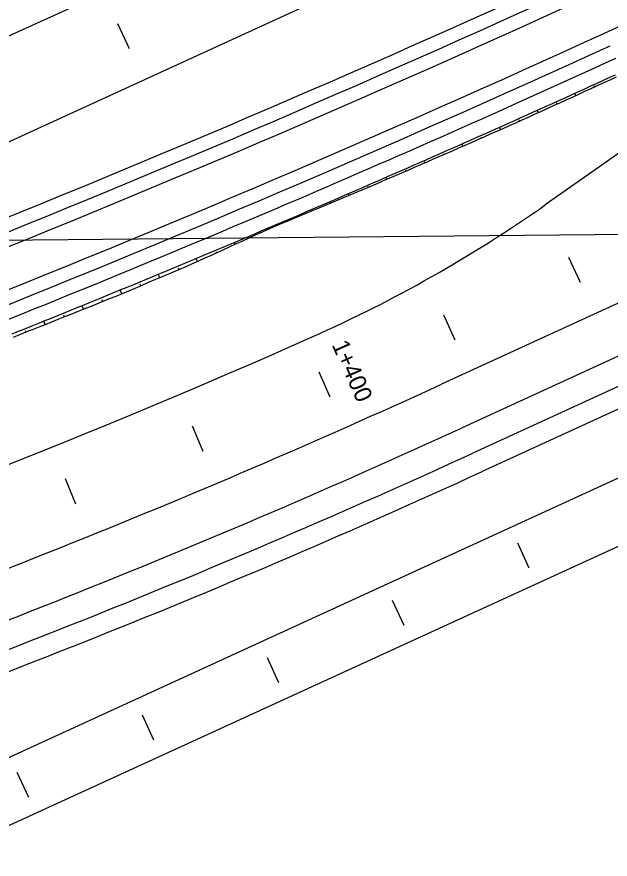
# Model space of a CAD drawing. Extents: x 6503541 to 6503743, y 5888004 to 5888145.
# Drawn here: x 6503623.308 to 6503624.343, y 5888063.051 to 5888064.519 of the extents above; entities that cross this region are included whole.
import ezdxf

# ---------------------------------------------------------------- set-up
doc = ezdxf.new("R2010")
doc.units = 0
doc.layers.add('12', color=7, linetype='Continuous')
doc.layers.add('tabela', color=7, linetype='Continuous')

msp = doc.modelspace()

# ---------------------------------------------------------------- linework, layer by layer
at = {"layer": '12'}
for p, q in [((6503624.3329, 5888064.491), (6503641.7733, 5888072.4873)), ((6503626.2595, 5888065.6608), (6503622.6026, 5888063.9841)), ((6503627.5672, 5888065.187), (6503623.1172, 5888063.1467)), ((6503626.551, 5888065.0262), (6503624.0486, 5888063.8788)), ((6503624.4101, 5888064.9977), (6503622.5325, 5888064.1368)), ((6503626.8132, 5888065.0011), (6503624.1036, 5888063.7588)), ((6503626.8282, 5888064.9684), (6503624.1186, 5888063.7261)), ((6503626.5424, 5888064.9298), (6503624.0836, 5888063.8025)), ((6503624.6932, 5888064.5176), (6503624.2296, 5888064.1916)), ((6503624.3147, 5888064.3992), (6503624.3155, 5888064.3974)), ((6503624.2828, 5888064.3824), (6503624.2811, 5888064.3861)), ((6503624.2492, 5888064.3693), (6503624.2501, 5888064.3674)), ((6503624.2173, 5888064.3525), (6503624.2155, 5888064.3565)), ((6503624.1836, 5888064.3397), (6503624.1845, 5888064.3377)), ((6503624.1517, 5888064.3229), (6503624.1498, 5888064.327)), ((6503624.1178, 5888064.3104), (6503624.1187, 5888064.3084)), ((6503624.0858, 5888064.2939), (6503624.0841, 5888064.2978)), ((6503624.052, 5888064.2813), (6503624.0528, 5888064.2795)), ((6503624.0198, 5888064.2651), (6503624.0182, 5888064.2687)), ((6503623.986, 5888064.2525), (6503623.9867, 5888064.2508)), ((6503623.9537, 5888064.2365), (6503623.9523, 5888064.2398)), ((6503623.92, 5888064.2238), (6503623.9207, 5888064.2221)), ((6503623.8875, 5888064.2082), (6503623.8863, 5888064.2111)), ((6503623.8537, 5888064.1956), (6503623.8543, 5888064.1944)), ((6503623.821, 5888064.1806), (6503623.8201, 5888064.1827)), ((6503623.7874, 5888064.1677), (6503623.7877, 5888064.1668)), ((6503623.7546, 5888064.1529), (6503623.7539, 5888064.1544)), ((6503623.689, 5888064.123), (6503623.6876, 5888064.1263)), ((6503623.7213, 5888064.1391), (6503623.7218, 5888064.1379)), ((6503623.6235, 5888064.0933), (6503623.6212, 5888064.0984)), ((6503623.6553, 5888064.1102), (6503623.6562, 5888064.1081)), ((6503625.4167, 5888064.0822), (6503623.1671, 5888063.0508)), ((6503623.5893, 5888064.0816), (6503623.5905, 5888064.0788)), ((6503623.5574, 5888064.0647), (6503623.5548, 5888064.0707)), ((6503623.5229, 5888064.0538), (6503623.5243, 5888064.0506)), ((6503623.4911, 5888064.0367), (6503623.4883, 5888064.0433)), ((6503623.4564, 5888064.0264), (6503623.4577, 5888064.0232)), ((6503623.4243, 5888064.0097), (6503623.4218, 5888064.016)), ((6503623.3897, 5888063.9994), (6503623.3909, 5888063.9964)), ((6503623.3574, 5888063.983), (6503623.3551, 5888063.9889)), ((6503623.3228, 5888063.9726), (6503623.324, 5888063.9697))]:
    msp.add_line(p, q, dxfattribs=at)
for points in [[(6503623.5045, 5888064.4637), (6503623.4845, 5888064.5073)], [(6503623.2999, 5888063.9667), (6503623.3111, 5888063.9712), (6503623.3223, 5888063.9757), (6503623.3335, 5888063.9802), (6503623.3447, 5888063.9847), (6503623.3558, 5888063.9892), (6503623.367, 5888063.9937), (6503623.3782, 5888063.9982), (6503623.3894, 5888064.0028), (6503623.4005, 5888064.0073), (6503623.4117, 5888064.0119), (6503623.4229, 5888064.0164), (6503623.434, 5888064.021), (6503623.4452, 5888064.0255), (6503623.4563, 5888064.0301), (6503623.4675, 5888064.0347), (6503623.4786, 5888064.0393), (6503623.4898, 5888064.0438), (6503623.5009, 5888064.0484), (6503623.5121, 5888064.053), (6503623.5232, 5888064.0576), (6503623.5343, 5888064.0622), (6503623.5455, 5888064.0668), (6503623.5566, 5888064.0715), (6503623.5678, 5888064.0761), (6503623.5789, 5888064.0807), (6503623.59, 5888064.0853), (6503623.6011, 5888064.09), (6503623.6123, 5888064.0946), (6503623.6234, 5888064.0993), (6503623.6345, 5888064.1039), (6503623.6456, 5888064.1086), (6503623.6567, 5888064.1133), (6503623.6678, 5888064.1179), (6503623.679, 5888064.1226), (6503623.6901, 5888064.1273), (6503623.7012, 5888064.132), (6503623.7123, 5888064.1367), (6503623.7234, 5888064.1414), (6503623.7345, 5888064.1461), (6503623.7456, 5888064.1508), (6503623.7567, 5888064.1555), (6503623.7677, 5888064.1603), (6503623.7788, 5888064.165), (6503623.7899, 5888064.1697), (6503623.801, 5888064.1745), (6503623.8121, 5888064.1792), (6503623.8232, 5888064.184), (6503623.8342, 5888064.1887), (6503623.8453, 5888064.1935), (6503623.8564, 5888064.1982), (6503623.8674, 5888064.203), (6503623.8785, 5888064.2078), (6503623.8896, 5888064.2126), (6503623.9006, 5888064.2174), (6503623.9117, 5888064.2222), (6503623.9228, 5888064.227), (6503623.9338, 5888064.2318), (6503623.9449, 5888064.2366), (6503623.9559, 5888064.2414), (6503623.967, 5888064.2462), (6503623.978, 5888064.251), (6503623.9891, 5888064.2559), (6503624.0001, 5888064.2607), (6503624.0111, 5888064.2656), (6503624.0222, 5888064.2704), (6503624.0332, 5888064.2753), (6503624.0442, 5888064.2801), (6503624.0553, 5888064.285), (6503624.0663, 5888064.2899), (6503624.0773, 5888064.2947), (6503624.0883, 5888064.2996), (6503624.0993, 5888064.3045), (6503624.1104, 5888064.3094), (6503624.1214, 5888064.3143), (6503624.1324, 5888064.3192), (6503624.1434, 5888064.3241), (6503624.1544, 5888064.329), (6503624.1654, 5888064.334), (6503624.1764, 5888064.3389), (6503624.1874, 5888064.3438), (6503624.1984, 5888064.3488), (6503624.2094, 5888064.3537), (6503624.2204, 5888064.3587), (6503624.2314, 5888064.3636), (6503624.2424, 5888064.3686), (6503624.2533, 5888064.3735), (6503624.2643, 5888064.3785), (6503624.2753, 5888064.3835), (6503624.2863, 5888064.3885), (6503624.2973, 5888064.3935), (6503624.3082, 5888064.3985), (6503624.3192, 5888064.4035), (6503624.3302, 5888064.4085), (6503624.3411, 5888064.4135), (6503624.3521, 5888064.4185)], [(6503623.3022, 5888063.9611), (6503623.3134, 5888063.9655), (6503623.3246, 5888063.97), (6503623.3358, 5888063.9744), (6503623.347, 5888063.9789), (6503623.3582, 5888063.9833), (6503623.3694, 5888063.9878), (6503623.3806, 5888063.9922), (6503623.3918, 5888063.9967), (6503623.403, 5888064.0012), (6503623.4142, 5888064.0057), (6503623.4254, 5888064.0102), (6503623.4366, 5888064.0147), (6503623.4478, 5888064.0192), (6503623.459, 5888064.0237), (6503623.4701, 5888064.0282), (6503623.4813, 5888064.0327), (6503623.4925, 5888064.0372), (6503623.5036, 5888064.0419), (6503623.5147, 5888064.0466), (6503623.5258, 5888064.0513), (6503623.5369, 5888064.056), (6503623.548, 5888064.0607), (6503623.5591, 5888064.0654), (6503623.5702, 5888064.0701), (6503623.5813, 5888064.0748), (6503623.5924, 5888064.0796), (6503623.6035, 5888064.0843), (6503623.6145, 5888064.0892), (6503623.6255, 5888064.0942), (6503623.6365, 5888064.0992), (6503623.6475, 5888064.1042), (6503623.6585, 5888064.1091), (6503623.6694, 5888064.1141), (6503623.6804, 5888064.1191), (6503623.6914, 5888064.1241), (6503623.7024, 5888064.1291), (6503623.7134, 5888064.1341), (6503623.7243, 5888064.1391), (6503623.7353, 5888064.1441), (6503623.7463, 5888064.1491), (6503623.7573, 5888064.1541), (6503623.7683, 5888064.1588), (6503623.7795, 5888064.1634), (6503623.7906, 5888064.168), (6503623.8018, 5888064.1726), (6503623.8129, 5888064.1772), (6503623.8241, 5888064.1818), (6503623.8352, 5888064.1864), (6503623.8463, 5888064.1911), (6503623.8575, 5888064.1957), (6503623.8686, 5888064.2003), (6503623.8797, 5888064.205), (6503623.8909, 5888064.2096), (6503623.902, 5888064.2143), (6503623.9131, 5888064.2189), (6503623.9242, 5888064.2236), (6503623.9353, 5888064.2284), (6503623.9463, 5888064.2333), (6503623.9574, 5888064.2381), (6503623.9684, 5888064.2429), (6503623.9795, 5888064.2477), (6503623.9906, 5888064.2524), (6503624.0016, 5888064.2572), (6503624.0127, 5888064.262), (6503624.0237, 5888064.2668), (6503624.0348, 5888064.2717), (6503624.0458, 5888064.2765), (6503624.0569, 5888064.2813), (6503624.0679, 5888064.2861), (6503624.079, 5888064.291), (6503624.09, 5888064.2958), (6503624.1011, 5888064.3006), (6503624.1121, 5888064.3055), (6503624.1231, 5888064.3103), (6503624.1342, 5888064.3152), (6503624.1452, 5888064.3201), (6503624.1562, 5888064.3249), (6503624.1672, 5888064.3299), (6503624.1782, 5888064.3348), (6503624.1892, 5888064.3398), (6503624.2002, 5888064.3448), (6503624.2112, 5888064.3498), (6503624.2222, 5888064.3547), (6503624.2331, 5888064.3597), (6503624.2441, 5888064.3647), (6503624.2551, 5888064.3697), (6503624.2661, 5888064.3747), (6503624.277, 5888064.3797), (6503624.288, 5888064.3847), (6503624.2989, 5888064.3897), (6503624.3099, 5888064.3948), (6503624.3209, 5888064.3998), (6503624.3318, 5888064.4048), (6503624.3428, 5888064.4099), (6503624.3538, 5888064.4148)], [(6503624.2911, 5888064.056), (6503624.2711, 5888064.0996)], [(6503624.0729, 5888063.956), (6503624.0529, 5888063.9996)], [(6503623.8346, 5888063.9008), (6503623.854, 5888063.8569)], [(6503623.6334, 5888063.7614), (6503623.6147, 5888063.8056)], [(6503623.4112, 5888063.6695), (6503623.3933, 5888063.714)], [(6503624.2017, 5888063.5582), (6503624.1817, 5888063.6018)], [(6503623.9835, 5888063.4582), (6503623.9635, 5888063.5018)], [(6503623.7654, 5888063.3581), (6503623.7454, 5888063.4018)], [(6503623.5472, 5888063.2581), (6503623.5272, 5888063.3017)], [(6503623.329, 5888063.1581), (6503623.309, 5888063.2017)]]:
    msp.add_lwpolyline(points, dxfattribs=at)
for centre, radius, start, end in [((6503614.3158, 5888086.3389), 23.9172, 291.63106, 294.63106), ((6503614.3158, 5888086.3389), 23.9412, 291.63106, 294.63106), ((6503614.3158, 5888086.3389), 23.9652, 291.63106, 294.63106), ((6503614.3158, 5888086.3389), 24.0348, 291.63106, 294.63106), ((6503614.3158, 5888086.3389), 24.0588, 291.63106, 294.63106), ((6503614.3158, 5888086.3389), 24.0828, 291.63106, 294.63106), ((6503622.8492, 5888066.1549), 2.4, 293.95, 305.1123), ((6503618.012, 5888077.0449), 14.316, 288.92046, 293.95001), ((6503618.012, 5888077.0449), 14.484, 288.9206, 294.63106), ((6503618.012, 5888077.0449), 14.568, 288.9206, 294.63118), ((6503618.012, 5888077.0449), 14.616, 288.92046, 294.63106), ((6503618.012, 5888077.0449), 14.652, 288.9206, 294.63106)]:
    msp.add_arc(centre, radius, start, end, dxfattribs=at)
at = {"layer": 'tabela'}
msp.add_line((6503627.0449, 5888064.165), (6503619.8094, 5888064.0974), dxfattribs=at)

# ---------------------------------------------------------------- texts
at = {"layer": '12'}
msp.add_text('1+400', height=0.03, rotation=293.8922, dxfattribs=at).set_placement((6503623.8569, 5888063.9478))

doc.saveas('drawing.dxf')
